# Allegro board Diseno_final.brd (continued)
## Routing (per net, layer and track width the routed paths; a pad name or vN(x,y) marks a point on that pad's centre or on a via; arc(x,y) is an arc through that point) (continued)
N151319: length 8.6
  TOP w0.381: 189.59,27.84 R43.1 ; 189.59,27.84 R42.2 ; 189.59,27.84 190.07,27.36 v1(191.19,27.36)
  BOTTOM w0.381: U164.3 v1(191.19,27.36)
N151343: length 14.8
  TOP w0.381: 264.64,105.77 266.04,104.37 267.11,104.37 269.77,107.04 C134.2 ; 264.64,105.77 264.64,107.48 264.62,107.51 U106.5 ; 264.64,105.77 264.64,103.25
N151347: length 10.8
  TOP w0.381: U36.3 195.25,38.76 189.59,33.1 R43.2
N151351: length 7.3
  TOP w0.381: U36.2 194.59,39.03 194.27,38.71 191.34,38.71 v1(190.8,39.24)
  BOTTOM w0.381: v1(190.8,39.24) R47.2
N151355: length 14.7
  TOP w0.381: 264.62,117.74 264.62,112.9 ; 264.62,117.74 266.09,119.21 266.09,121.77 265.07,122.78 R104.1 ; 264.62,117.74 264.22,118.14 U105.6
N151359: length 13.9
  TOP w0.381: R45.2 195.25,46.25 ; 195.25,46.25 U36.6 ; 195.25,46.25 195.76,45.75 v1(197.33,45.75)
  BOTTOM w0.381: v1(197.33,45.75) 197.33,44.4 196.25,43.32 R47.1
N151379: length 13.2
  TOP w0.381: 195.25,51.64 R45.1 ; 195.25,51.64 195.68,51.21 199.57,51.21 202.34,53.98 C49.1 ; 195.25,51.64 R41.2
N151407: length 35.2
  TOP w0.381: C49.2 202.34,64.69 198.27,68.76 196.01,68.76 195.28,68.02 ; 195.28,69.93 R44.2 ; 195.28,69.93 194.77,70.43 193.27,70.43 v1(190.35,67.51) ; 195.28,69.93 195.28,68.02 ; 195.28,68.02 U35.6
  BOTTOM w0.381: R46.1 v1(190.35,67.51)
N151415: length 12
  TOP w0.381: 257.73,31.22 257.05,31.9 v1(256.41,31.9) ; 257.73,31.22 R106.2 ; 257.73,31.22 R107.1
  BOTTOM w0.381: v1(256.41,31.9) 257.15,31.9 257.68,31.37 ; 257.68,31.37 D27.A ; 257.68,31.37 D28.C
N151419: length 14.2
  TOP w0.381: v1(193.09,59.33) 194.12,59.33 194.61,59.83 U35.2
  BOTTOM w0.381: 190.35,56.59 R46.2 ; 190.35,56.59 R48.1 ; 190.35,56.59 v1(193.09,59.33)
N151447: length 14.6
  TOP w0.381: U35.7 194.61,67.16 194.23,67.54 191.67,67.54 190.58,66.45 C47.2 189.37,65.29 189.36,65.3 v1(187.83,65.3)
  BOTTOM w0.381: v1(187.83,65.3) 187.83,62.8 186.88,61.85 U33.2
N151475: length 15.9
  TOP w0.381: v1(190.86,48.17) C46.2 193.96,46.12 194.59,45.49 U36.7
  BOTTOM w0.381: U32.2 187.34,52.94 188.48,51.8 188.48,48.65 188.96,48.17 v1(190.86,48.17)
N151623: length 32.5
  TOP w0.381: 263.04,108.31 263.04,107.57 262.39,106.92 U104.2 ; 263.04,108.31 263.04,109.58 262.15,110.46 258.08,110.46 256.06,112.48 R108.2 ; 263.04,108.31 262.43,108.92 v1(261.54,108.92)
  BOTTOM w0.381: v1(261.54,108.92) 261.09,108.92 259.46,107.29 259.46,98.65 256.01,95.2 R105.1
N151641: length 8.8
  TOP w0.381: U105.2 257.8,118.8 257.07,119.52 257.07,122.15 257.71,122.78 R104.2
N151661: length 5.1
  TOP w0.381: R108.1 256.06,117.32 256.87,118.14 U105.3
N151733: length 19.9
  TOP w0.381: v1(197.59,39.98) 198.53,39.98 198.54,39.99 C51.2 199.75,38.91 199.11,38.28 196.37,38.28 195.88,38.76 U36.4
  BOTTOM w0.381: U37.4 198.97,49.45 198.48,48.96 198.48,42.19 197.59,41.3 v1(197.59,39.98)
N151737: length 9.2
  TOP w0.381: v1(197.28,57.73) 197.72,58.17 197.72,58.18 198.53,58.99 C54.2 196.68,59.78 195.91,60.54 U35.4
  BOTTOM w0.381: U38.4 198.97,57.76 198.95,57.73 v1(197.28,57.73)
N151741: length 4.2
  TOP w0.381: R44.1 194.21,74.03 194.2,74.02 U34.3
N151759: length 76.9
  TOP w0.381: v1(186.66,73.05) 187.29,73.05 187.31,73.08 U34.5 ; U172.2 124.43,84.45 124.44,84.45 v1(125.07,84.45)
  BOTTOM w0.381: v1(186.66,73.05) 168.43,73.05 164.69,69.32 162.18,69.32 157.12,74.37 145.77,74.37 135.69,84.45 v1(125.07,84.45)
N151833: length 11.6
  TOP w0.381: U107.7 264.64,97.43 265.84,96.24 C133.2 267.6,98.57 267.59,98.58 v1(267.59,99.24)
  BOTTOM w0.381: v1(267.59,99.24) 267.59,100.41 268.55,101.37 U103.2
N152345: length 8.9
  TOP w0.381: R52.2 196.39,27.79 ; 196.39,27.79 R54.1 ; 196.39,27.79 196.8,27.38 v1(197.87,27.38)
  BOTTOM w0.381: U165.3 v1(197.87,27.38)
N152363: length 14.8
  TOP w0.381: 264.64,140.03 U115.2 ; 264.64,140.03 264.64,141.74 264.62,141.77 U114.5 ; 264.64,140.03 266.04,138.63 267.11,138.63 269.77,141.3 C143.2
N152375: length 14.7
  TOP w0.381: 264.62,152.01 266.09,153.48 266.09,156.03 265.07,157.05 R109.1 ; 264.62,152.01 U114.4 ; 264.62,152.01 264.22,152.4 U113.6
N152387: length 59.2
  TOP w0.381: R54.2 196.39,32.87 208.03,44.5 208.03,65.91 195.28,78.66 195.28,79.62 195.25,79.64 U43.3
N152391: length 7.9
  TOP w0.381: U43.2 194.59,79.4 194.26,79.07 191.24,79.07 190.83,79.48 v1(190.83,80.26)
  BOTTOM w0.381: v1(190.83,80.26) 190.83,80.89 190.8,80.91 R56.2
N152399: length 13.9
  TOP w0.381: v1(197.33,86.36) 195.76,86.36 195.25,86.87 ; 195.25,86.87 R50.2 ; 195.25,86.87 U43.6
  BOTTOM w0.381: R56.1 196.25,83.93 197.33,85.01 v1(197.33,86.36)
N152403: length 146.9
  TOP w0.381: 263.98,129.03 263.98,127.61 279.25,112.34 279.25,55.7 262.64,39.09 R111.1 ; 263.98,129.03 264.85,129.9 v1(264.92,129.9) ; 263.98,129.03 U115.6 ; 269.77,149.1 v1(273.63,145.24) ; 269.77,149.1 269.77,149.3 268.38,150.7 266.6,150.7 265.25,149.35 U114.3 ; 269.77,149.1 C143.1
  BOTTOM w0.381: v1(273.63,145.24) 265.91,137.52 265.91,130.89 v1(264.92,129.9)
N152419: length 13.2
  TOP w0.381: 195.25,92.25 195.68,91.82 199.57,91.82 202.34,94.59 C59.1 ; 195.25,92.25 R50.1 ; 195.25,92.25 R51.2
N152423: length 12.8
  TOP w0.381: 195.25,98.5 194.28,97.54 192.25,97.54 191.58,96.86 C60.2 ; 195.25,98.5 R51.1 ; 195.25,98.5 195.28,98.53 U42.3
N152441: length 11.5
  TOP w0.381: R112.1 262.64,31.51 ; 262.64,31.51 262.25,31.89 261.61,31.89 v1(261.57,31.93) ; 262.64,31.51 R111.2
  BOTTOM w0.381: v1(261.57,31.93) 261.61,31.89 262.19,31.89 262.66,31.42 ; 262.66,31.42 D30.C ; 262.66,31.42 D29.A
N152447: length 35.6
  TOP w0.381: 195.28,108.64 195.28,110.54 ; 195.28,108.64 U42.6 ; 195.28,108.64 196.01,109.37 198.27,109.37 202.34,105.31 C59.2 ; 195.28,110.54 194.77,111.05 192.57,111.05 190.35,108.83 v1(190.35,108.2) ; 195.28,110.54 R53.2
  BOTTOM w0.381: R55.1 v1(190.35,108.2)
N152459: length 14.2
  TOP w0.381: U42.2 194.61,100.44 194.12,99.95 v1(193.09,99.95)
  BOTTOM w0.381: 190.35,97.21 R57.1 ; 190.35,97.21 v1(193.09,99.95) ; 190.35,97.21 R55.2
N152487: length 14.4
  TOP w0.381: U42.7 194.61,107.67 194.23,108.05 191.64,108.05 190.58,106.98 C57.2 189.37,105.91 189.36,105.92 v1(187.83,105.92)
  BOTTOM w0.381: v1(187.83,105.92) 187.83,103.42 186.88,102.46 U40.2
N152515: length 15.9
  TOP w0.381: U43.7 194.59,86.11 193.96,86.73 C56.2 v1(190.86,88.79)
  BOTTOM w0.381: v1(190.86,88.79) 188.96,88.79 188.48,89.27 188.48,92.42 187.34,93.56 U39.2
N152649: length 32.5
  TOP w0.381: v1(261.54,143.18) 262.43,143.18 263.04,142.57 ; R113.2 256.06,146.75 258.08,144.73 262.15,144.73 263.04,143.84 263.04,142.57 ; 263.04,142.57 263.04,141.84 262.39,141.19 U112.2
  BOTTOM w0.381: v1(261.54,143.18) 261.09,143.18 259.46,141.55 259.46,132.92 256.01,129.47 R110.1
N152661: length 8.8
  TOP w0.381: U113.2 257.8,153.06 257.07,153.78 257.07,156.41 257.71,157.05 R109.2
N152681: length 5.1
  TOP w0.381: U113.3 256.87,152.4 256.06,151.59 R113.1
N152773: length 19.9
  TOP w0.381: v1(197.59,80.59) 198.53,80.59 198.54,80.6 C61.2 199.75,79.53 199.11,78.89 196.37,78.89 195.88,79.38 U43.4
  BOTTOM w0.381: U44.4 198.97,90.07 198.48,89.57 198.48,82.8 197.59,81.92 v1(197.59,80.59)
N152777: length 9.2
  TOP w0.381: U42.4 195.91,101.16 196.68,100.38 197.31,100.38 197.32,100.39 C64.2 198.53,99.6 197.72,98.8 197.72,98.79 v1(197.28,98.35)
  BOTTOM w0.381: U45.4 198.97,98.37 198.95,98.35 v1(197.28,98.35)
N152781: length 4.2
  TOP w0.381: U41.3 194.2,114.63 194.21,114.64 R53.1
N152799: length 81.5
  TOP w0.381: U173.2 112.9,110.54 115.27,108.18 130.28,108.18 v1(131.32,109.22) ; U41.5 v1(186.87,113.69)
  BOTTOM w0.381: v1(186.87,113.69) 170.08,113.69 165.61,109.22 v1(131.32,109.22)
N152853: length 11.6
  TOP w0.381: v1(267.59,133.5) 267.59,132.85 267.6,132.84 C142.2 265.84,130.51 264.64,131.7 U115.7
  BOTTOM w0.381: U111.2 268.55,135.64 267.59,134.67 v1(267.59,133.5)
N153383: length 14.8
  TOP w0.381: C152.2 269.77,175.34 267.11,172.67 266.04,172.67 264.64,174.07 ; U122.5 264.62,175.81 264.64,175.78 264.64,174.07 ; 264.64,174.07 U123.2
N153389: length 9
  TOP w0.381: 203,27.76 R63.1 ; 203,27.76 R59.2 ; 203,27.76 203.38,27.38 v1(204.47,27.38)
  BOTTOM w0.381: U166.3 v1(204.47,27.38)
N153395: length 14.7
  TOP w0.381: R114.1 265.07,191.08 266.09,190.07 266.09,187.52 264.62,186.04 ; 264.62,186.04 264.22,186.44 U121.6 ; 264.62,186.04 U122.4
N153423: length 182.6
  TOP w0.381: v1(273.93,179.29) 273.49,179.73 273.44,179.73 269.82,183.34 269.77,183.34 ; U122.3 265.25,183.39 266.6,184.73 268.38,184.73 269.77,183.34 ; 269.77,183.34 C152.1 ; 263.98,163.07 263.98,161.29 283.44,141.83 283.44,56.21 268.17,40.94 R116.1 ; 263.98,163.07 264.85,163.93 v1(264.92,163.93) ; 263.98,163.07 U123.6
  BOTTOM w0.381: v1(273.93,179.29) 273.49,178.85 273.49,178.85 265.91,171.27 265.91,164.92 v1(264.92,163.93)
N153431: length 99.9
  TOP w0.381: U50.3 195.25,119.56 211.58,103.23 211.58,41.91 203,33.32 R63.2
N153435: length 7.6
  TOP w0.381: v1(190.8,120.95) 190.8,120.14 191.19,119.76 194.21,119.76 194.59,120.14 U50.2
  BOTTOM w0.381: v1(190.8,120.95) R65.2
N153443: length 13.9
  TOP w0.381: 195.25,127.41 R61.2 ; 195.25,127.41 195.76,126.9 v1(197.33,126.9) ; 195.25,127.41 U50.6
  BOTTOM w0.381: R65.1 196.25,124.47 197.33,125.55 v1(197.33,126.9)
N153455: length 12.9
  TOP w0.381: 268.17,31.29 R116.2 ; 268.17,31.29 267.54,31.93 v1(266.67,31.93) ; 268.17,31.29 R117.1
  BOTTOM w0.381: 268.17,31.32 D31.A ; 268.17,31.32 D32.C ; 268.17,31.32 267.56,31.93 v1(266.67,31.93)
N153463: length 13.2
  TOP w0.381: 195.25,132.79 R61.1 ; 195.25,132.79 R62.2 ; 195.25,132.79 195.68,132.36 199.57,132.36 202.34,135.13 C69.1
N153467: length 12.8
  TOP w0.381: R62.1 195.25,139.04 ; 195.25,139.04 194.28,138.07 192.25,138.07 191.58,137.4 C70.2 ; 195.25,139.04 195.28,139.06 U49.3
N153491: length 34.9
  TOP w0.381: 195.28,149.17 196.01,149.91 198.27,149.91 202.34,145.85 C69.2 ; 195.28,149.17 U49.6 ; 195.28,149.17 195.28,151.08 ; v1(190.35,148.41) 193.34,151.41 194.94,151.41 195.28,151.08 ; 195.28,151.08 R60.2
  BOTTOM w0.381: R64.1 v1(190.35,148.41)
N153503: length 14.2
  TOP w0.381: v1(193.09,140.49) 194.12,140.49 194.61,140.98 U49.2
  BOTTOM w0.381: v1(193.09,140.49) 190.35,137.74 ; 190.35,137.74 R64.2 ; 190.35,137.74 R66.1
N153531: length 14.7
  TOP w0.381: v1(187.83,146.46) 189.36,146.46 189.37,146.45 C67.2 190.58,147.47 191.92,148.82 194.23,148.82 194.61,148.44 U49.7
  BOTTOM w0.381: v1(187.83,146.46) 187.83,143.95 186.88,143 U47.2
N153559: length 15.9
  TOP w0.381: v1(190.86,129.32) C66.2 193.96,127.27 194.59,126.64 U50.7
  BOTTOM w0.381: v1(190.86,129.32) 188.96,129.32 188.48,129.81 188.48,132.96 187.34,134.09 U46.2
N153663: length 32.5
  TOP w0.381: 263.04,176.61 262.43,177.22 v1(261.54,177.22) ; 263.04,176.61 263.04,177.88 262.15,178.77 258.08,178.77 256.06,180.78 R118.2 ; 263.04,176.61 263.04,175.87 262.39,175.22 U120.2
  BOTTOM w0.381: v1(261.54,177.22) 261.09,177.22 259.46,175.59 259.46,166.95 256.01,163.5 R115.1
N153681: length 8.8
  TOP w0.381: R114.2 257.71,191.08 257.07,190.45 257.07,187.82 257.8,187.1 U121.2
N153701: length 5.1
  TOP w0.381: U121.3 256.87,186.44 256.06,185.62 R118.1
N153817: length 19.9
  TOP w0.381: U50.4 195.88,119.91 196.37,119.43 199.11,119.43 199.75,120.07 C71.2 198.54,121.14 198.53,121.13 v1(197.59,121.13)
  BOTTOM w0.381: v1(197.59,121.13) 197.59,122.45 198.48,123.34 198.48,130.11 198.97,130.61 U51.4
N153821: length 9.2
  TOP w0.381: U49.4 195.91,141.69 196.68,140.93 C74.2 198.53,140.14 197.72,139.34 197.72,139.33 v1(197.28,138.89)
  BOTTOM w0.381: U52.4 198.97,138.91 198.95,138.89 v1(197.28,138.89)
N153825: length 4.2
  TOP w0.381: U48.3 194.2,155.17 194.21,155.18 R60.1
N153843: length 78.8
  TOP w0.381: U174.2 122.65,140.77 122.66,140.77 v1(123.34,140.77) ; U48.5 v1(186.08,154.23)
  BOTTOM w0.381: v1(186.08,154.23) 170.05,154.23 165.91,150.09 162.59,150.09 157.56,155.12 156.54,155.12 155.7,154.28 145.92,154.28 132.41,140.77 v1(123.34,140.77)
N153873: length 11.6
  TOP w0.381: U123.7 264.64,165.74 265.84,164.54 C151.2 267.6,166.87 267.59,166.88 v1(267.59,167.54)
  BOTTOM w0.381: v1(267.59,167.54) 267.59,168.71 268.55,169.67 U119.2
N154443: length 8.3
  TOP w0.381: R72.1 209.22,27.74 ; 209.22,27.74 209.58,27.38 v1(210.44,27.38) ; 209.22,27.74 R71.2
  BOTTOM w0.381: v1(210.44,27.38) 209.64,27.38 209.61,27.41 U167.3
N154471: length 142.2
  TOP w0.381: U56.3 195.25,161.06 215.65,140.67 215.65,40.26 209.22,33.83 R72.2
N154475: length 8
  TOP w0.381: U56.2 194.59,161.61 193.81,160.83 191.34,160.83 v1(190.8,161.37)
  BOTTOM w0.381: v1(190.8,161.37) R74.2
N154483: length 13.9
  TOP w0.381: R69.2 195.25,168.83 ; 195.25,168.83 195.76,168.33 v1(197.33,168.33) ; 195.25,168.83 195.25,167
  BOTTOM w0.381: v1(197.33,168.33) 197.33,166.98 196.25,165.9 R74.1
N154503: length 13.2
  TOP w0.381: 195.25,174.22 R69.1 ; 195.25,174.22 195.68,173.79 199.57,173.79 202.34,176.56 C79.1 ; 195.25,174.22 R70.2
N154507: length 12.8
  TOP w0.381: R70.1 195.25,180.47 ; 195.25,180.47 195.28,180.49 U57.3 ; 195.25,180.47 194.28,179.5 192.25,179.5 191.58,178.83 C80.2
N154531: length 35.1
  TOP w0.381: C79.2 202.34,187.27 198.27,191.34 196.01,191.34 195.28,190.6 ; 195.28,190.6 U57.6 ; 195.28,190.6 195.28,192.51 ; 195.28,192.51 R68.2 ; 195.28,192.51 194.77,193.01 v1(193.4,193.01)
  BOTTOM w0.381: R73.1 190.35,189.97 v1(193.4,193.01)
N154543: length 14.2
  TOP w0.381: U57.2 194.61,182.41 194.12,181.91 v1(193.09,181.91)
  BOTTOM w0.381: v1(193.09,181.91) 190.35,179.17 ; 190.35,179.17 R75.1 ; 190.35,179.17 R73.2
N154571: length 15.7
  TOP w0.381: v1(187.83,187.88) 189.36,187.88 189.37,187.87 C77.2 190.58,189.87 191.34,190.63 194.01,190.63 194.61,190.02 U57.7
  BOTTOM w0.381: U54.2 186.88,184.43 187.83,185.38 v1(187.83,187.88)
N154599: length 15.9
  TOP w0.381: 194.59,167 194.59,168.07 193.96,168.7 C76.2 v1(190.86,170.75)
  BOTTOM w0.381: U53.2 187.34,175.52 188.48,174.38 188.48,171.23 188.96,170.75 v1(190.86,170.75)
N154857: length 19.9
  TOP w0.381: v1(197.59,162.56) 198.53,162.56 198.54,162.57 C81.2 199.75,161.49 199.11,160.86 196.37,160.86 195.88,161.34 U56.4
  BOTTOM w0.381: v1(197.59,162.56) 197.59,163.88 198.48,164.77 198.48,171.54 198.97,172.03 U58.4
N154861: length 9.2
  TOP w0.381: v1(197.28,180.31) 197.72,180.75 197.72,180.76 198.53,181.57 C84.2 196.56,182.36 195.91,183.01 U57.4
  BOTTOM w0.381: v1(197.28,180.31) 198.95,180.31 198.97,180.34 U59.4
N154865: length 4.2
  TOP w0.381: R68.1 194.21,196.61 194.2,196.6 U55.3
N154883: length 80.2
  TOP w0.381: v1(183.74,194.84) 184.56,195.66 U55.5 ; U175.2 123.18,168.94 123.18,168.93 v1(123.87,168.93)
  BOTTOM w0.381: v1(123.87,168.93) 125.07,168.93 147.04,190.91 159.89,190.91 163.83,194.84 v1(183.74,194.84)
N183704: length 133.9
  TOP w0.381: v1(234.95,83.74) 234.31,83.74 233.38,82.8 U65.2 ; v1(121.67,96.8) U176.4
  BOTTOM w0.381: v1(121.67,96.8) 128.85,96.8 147.08,78.57 165.7,78.57 167.84,76.43 193.45,76.43 197.08,72.8 198.25,72.8 209.19,83.74 230.89,83.74 230.91,83.76 231.42,83.76 231.44,83.74 v1(234.95,83.74)
N189418: length 4.1
  TOP w0.381: U168.4 106.62,84.04 105.23,82.65 R4.1
N189529: length 12.8
  TOP w0.381: R40.1 105.04,85.14 105.29,85.39 U172.4
N189636: length 13.4
  TOP w0.381: U169.4 113.82,114.12 112.14,112.45 R13.1
N189665: length 4.1
  TOP w0.381: U173.4 106.35,111.48 105.05,110.19 R49.1
N189787: length 4
  TOP w0.381: R22.1 105.67,137.97 106.69,138.99 U170.4
N189811: length 13.4
  TOP w0.381: U174.4 115.4,141.71 113.72,140.03 R58.1
N189953: length 3.7
  TOP w0.381: R31.1 105.04,173.08 105.3,173.34 U171.4
N189979: length 13.8
  TOP w0.381: R67.1 104.97,168.33 105.35,167.94 113,167.94 114.94,169.88 U175.4
N190257: length 129.3
  TOP w0.381: v1(122.63,125.19) 121.98,125.19 121.97,125.18 U177.4 ; v1(234.95,115.42) 234.31,115.42 233.38,114.48 233.38,112.9
  BOTTOM w0.381: v1(122.63,125.19) 130.81,125.19 136.91,119.1 190.7,119.1 201.51,108.3 202.35,108.3 209.83,115.77 233.97,115.77 234.33,115.42 v1(234.95,115.42)
N190390: length 177.4
  TOP w0.381: U180.4 111.19,102.2 111.2,102.18 v1(113.44,102.18) ; v1(267.49,83.74) 266.85,83.74 265.91,82.8 U98.2
  BOTTOM w0.381: v1(267.49,83.74) 265.73,83.74 259.38,90.09 214.45,90.09 203.68,79.32 147.6,79.32 124.74,102.18 v1(113.44,102.18)
N190419: length 131.7
  TOP w0.381: v1(234.95,149.68) 234.31,149.68 233.38,148.74 U81.2 ; U178.4 123.15,153.34 123.15,153.34 v1(123.77,153.34)
  BOTTOM w0.381: v1(123.77,153.34) 139.5,153.34 146.53,160.38 164.11,160.38 167.08,157.4 193.27,157.4 199.8,150.88 201.83,150.88 208.23,157.28 227.36,157.28 v1(234.95,149.68)
N190547: length 170.2
  TOP w0.381: v1(267.49,115.42) 266.85,115.42 265.91,114.48 265.91,112.9 ; v1(112.88,129.67) 111.2,129.67 111.19,129.67 U181.4
  BOTTOM w0.381: v1(112.88,129.67) 127.41,129.67 137.34,119.74 206.71,119.74 209.93,116.51 237.19,116.51 241.45,120.78 259.92,120.78 265.28,115.42 v1(267.49,115.42)
N190594: length 131.9
  TOP w0.381: U90.2 233.38,182.78 234.31,183.72 v1(234.95,183.72) ; v1(124.59,181.52) 123.97,181.52 123.95,181.51 U179.4
  BOTTOM w0.381: v1(234.95,183.72) 231.93,183.72 217.55,198.09 149.81,198.09 133.24,181.52 v1(124.59,181.52)
N190692: length 172.3
  TOP w0.381: v1(113.44,157.18) 111.21,157.18 111.19,157.15 U182.4 ; v1(267.49,149.68) 266.85,149.68 265.91,148.74 U114.2
  BOTTOM w0.381: v1(267.49,149.68) 264.39,149.68 256.08,157.99 207.87,157.99 201.6,151.71 199.95,151.71 193.55,158.12 167.46,158.12 164.49,161.09 146.23,161.09 142.32,157.18 v1(113.44,157.18)
N190839: length 172.9
  TOP w0.381: U183.4 113.89,184.63 113.89,184.62 v1(114.66,184.62) ; v1(267.49,183.72) 266.85,183.72 265.91,182.78 U122.2
  BOTTOM w0.381: v1(267.49,183.72) 252.37,198.83 149.58,198.83 135.37,184.62 v1(114.66,184.62)
N222678: length 13.8
  TOP w0.381: v1(226.31,79.81) 226.31,80.87 226.3,80.89 C91.2 226.3,83.3 224.74,84.85 224.74,85.47 225.09,85.83 U66.4
  BOTTOM w0.381: v1(226.31,79.81) 226.31,78.97 224.99,77.65 U68.4
N222700: length 13.8
  TOP w0.381: U97.4 257.63,85.83 257.28,85.47 257.28,84.85 258.84,83.3 C127.2 258.84,80.89 258.85,80.87 v1(258.85,79.81)
  BOTTOM w0.381: v1(258.85,79.81) 258.85,78.97 257.53,77.65 U100.4
N224115: length 12.2
  TOP w0.381: v1(257.23,70.26) 258.11,70.26 258.12,70.25 C129.2 259.64,71.32 261.52,73.2 262.97,73.2 263.35,72.82 U99.4
  BOTTOM w0.381: U101.4 v1(257.23,70.26)
N224126: length 12.2
  TOP w0.381: U67.4 230.81,72.82 230.43,73.2 228.98,73.2 227.1,71.32 C93.2 225.59,70.25 225.58,70.26 v1(224.69,70.26)
  BOTTOM w0.381: U69.4 v1(224.69,70.26)
N225476: length 13.9
  TOP w0.381: U73.4 225.09,117.5 224.74,117.15 224.74,116.53 226.3,114.97 C100.2 226.3,112.56 226.31,112.55 v1(226.31,111.15)
  BOTTOM w0.381: U76.4 225.11,109.32 226.31,110.53 v1(226.31,111.15)
N225794: length 13.8
  TOP w0.381: U105.4 257.63,117.5 257.28,117.15 257.28,116.53 258.84,114.97 C136.2 258.84,112.56 258.85,112.55 v1(258.85,111.48)
  BOTTOM w0.381: U108.4 257.53,109.32 258.85,110.64 v1(258.85,111.48)
N226643: length 12.2
  TOP w0.381: v1(224.69,101.93) 225.58,101.93 225.59,101.92 C102.2 227.1,103 228.98,104.88 230.43,104.88 230.81,104.5 230.81,103.25
  BOTTOM w0.381: U77.4 v1(224.69,101.93)
N226662: length 12.2
  TOP w0.381: v1(257.23,101.93) 258.11,101.93 258.12,101.92 C138.2 259.64,103 261.52,104.88 262.97,104.88 263.35,104.5 263.35,103.25
  BOTTOM w0.381: U109.4 v1(257.23,101.93)
N227931: length 13.8
  TOP w0.381: v1(226.31,145.75) 226.31,146.81 226.3,146.83 C109.2 226.3,149.23 224.74,150.79 224.74,151.41 225.09,151.76 U83.4
  BOTTOM w0.381: v1(226.31,145.75) 226.31,144.91 224.99,143.59 U84.4
N229062: length 12.2
  TOP w0.381: U82.4 230.81,138.76 230.43,139.14 228.98,139.14 227.1,137.26 C111.2 225.59,136.19 225.58,136.19 v1(224.69,136.19)
  BOTTOM w0.381: U85.4 v1(224.69,136.19)
N230061: length 13.8
  TOP w0.381: v1(226.31,179.78) 226.31,180.85 226.3,180.86 C118.2 226.3,183.27 224.74,184.83 224.74,185.45 225.09,185.8 U89.4
  BOTTOM w0.381: v1(226.31,179.78) 226.31,178.94 224.99,177.62 U92.4
N231120: length 12.2
  TOP w0.381: v1(224.69,170.23) 225.58,170.23 225.59,170.22 C120.2 227.1,171.3 228.98,173.18 230.43,173.18 230.81,172.8 U91.4
  BOTTOM w0.381: U93.4 v1(224.69,170.23)
N231215: length 13.8
  TOP w0.381: U121.4 257.63,185.8 257.28,185.45 257.28,184.83 258.84,183.27 C154.2 258.84,180.86 258.85,180.85 v1(258.85,179.78)
  BOTTOM w0.381: U124.4 257.53,177.62 258.85,178.94 v1(258.85,179.78)
N232018: length 12.2
  TOP w0.381: v1(257.23,170.23) 258.11,170.23 258.12,170.22 C156.2 259.64,171.3 261.52,173.18 262.97,173.18 263.35,172.8 U123.4
  BOTTOM w0.381: 254.43,170.23 v1(257.23,170.23)
N233016: length 13.8
  TOP w0.381: U113.4 257.63,151.76 257.28,151.41 257.28,150.79 258.84,149.23 C145.2 258.84,146.83 258.85,146.81 v1(258.85,145.75)
  BOTTOM w0.381: v1(258.85,145.75) 258.85,144.91 257.53,143.59 U116.4
N233815: length 12.2
  TOP w0.381: U115.4 263.35,138.76 262.97,139.14 261.52,139.14 259.64,137.26 C147.2 258.12,136.19 258.11,136.19 v1(257.23,136.19)
  BOTTOM w0.381: U117.4 v1(257.23,136.19)

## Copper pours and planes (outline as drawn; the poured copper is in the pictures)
3V3 on VCC: 137.31,63.07 123.9,63.07 124.1,63.27 124.1,188.72 104.5,188.72 104.47,188.7 104.47,164.16 52.98,164.16 52.27,163.45 52.27,144.27 53.59,142.95 104.37,142.95 104.47,143.05 104.47,63.09 19.53,63.09 19.51,63.12 19.51,12.98 19.89,12.6 135.81,12.6 137.72,14.5 137.72,62.66
3V3ADC on VCC: 156.16,197.84 156.11,197.89 155.91,197.69 155.91,68.3 161.85,68.3 161.98,68.43 161.98,195.07 161.9,195.15 191.19,195.15 191.26,195.07 191.26,68.5 191.47,68.3 196.27,68.3 196.47,68.5 196.47,197.54 196.16,197.84
3V3DAC on VCC: 266.78,174.24 266.78,57.15 266.8,57.12 275.31,57.12 275.31,177.67 234.26,177.67 234.19,177.6 234.19,175.41 234.15,175.37 234.15,57.62 234.49,57.28 240.44,57.28 240.44,174.24
5VU on VCC: 40.51,192.53 41.81,191.24 41.81,121.74 41.4,121.34 13.44,121.34 12.37,122.4 12.37,144.86 12.45,144.93 12.45,191.69 13.3,192.54 13.31,192.53
5VU on VCC: 272.8,12.73 272.8,22.25 272.67,22.38 180.59,22.38 180.59,22.33 180.64,22.28 179.91,21.54 142.32,21.54 141.76,22.1 141.76,189.79 141.35,190.2 141.35,190.22 125.63,190.22 124.87,189.46 124.87,64.59 125.43,64.03 137.69,64.03 138.4,63.32 138.4,13.34 139.01,12.73 272.36,12.73 272.77,13.13 272.77,12.7
+5V on VCC: 277.29,177.62 285.57,177.62 285.57,177.57 286.13,177.01 286.13,42.72 284.96,41.55 180.26,41.55 180.14,41.68 179.63,41.17 179.63,22.86 178.74,21.97 142.54,21.97 142.06,22.45 142.06,189.79 142.1,189.83 142.1,190.28 141.87,190.51 104.15,190.51 102.34,188.7 102.34,182.5 101.57,181.74 54.74,181.74 53.31,183.16 53.31,192.91 54.86,194.46 145.52,194.46 150.37,189.61 150.37,32.16 150.44,32.08 154,32.08 154.23,31.85 154.23,27.66 154.38,27.51 154.38,27.48 170.64,27.48 171.2,28.04 171.2,186.92 171.53,187.25 178.79,187.25 179.07,186.97 179.07,48.97 180.19,47.85 243.48,47.85 244.2,48.56 244.2,169.75 244.17,169.77 244.4,170 249.45,170 249.73,169.72 249.73,54.76 250.09,54.41 275.21,54.41 276.58,55.78 276.58,176.99 276.66,176.99
-5V on VCC: 241.22,173.84 257.91,173.84 257.94,173.86 257.94,55.75 257.76,55.58 252.78,55.58 252.55,55.8 252.55,170.31 244.12,170.31 243.84,170.03 243.84,54.03 243.61,53.8 218.41,53.8 218.41,176.28 218.44,176.3 225.48,176.3 225.48,175.95 225.46,175.96 225.46,173.06 225.5,173.02 225.5,56.41 240.84,56.41 241.2,56.06 241.2,173.86
-5V on VCC: 196.82,188.9 225.27,188.9 225.48,189.1 225.48,176.3 225.43,176.25 204.32,176.25 204.24,176.33 204.24,51.33 204.06,51.16 181.74,51.16 181.71,51.18 181.76,51.23 181.76,188.87 181.64,189 169.75,189 169.77,188.98 169.77,51.41 169.85,51.33 169.85,28.68 155.32,28.68 155.32,32.54 155.27,32.59 150.77,32.59 150.67,32.69 150.67,35.59 151.13,35.59 151.13,189.76 151.03,189.76 145.77,195.02 53.67,195.02 51.36,192.71 51.36,183.03 54.89,179.5 64.64,179.5 65.41,178.74 65.41,170.59 64.39,169.57 43.36,169.57 42.44,170.48 42.44,199.39 155.37,199.39 155.65,199.11 155.65,67.84 155.96,67.54 161.34,67.54 161.35,67.53 162.37,67.53 162.38,67.51 162.41,67.51 162.86,67.97 162.86,194.41 189.13,194.41 189.2,194.34 189.2,60.5 189.43,60.27 196.8,60.27 196.8,188.93
A_GND on GND: 286.59,199.39 286.59,12.29 286.41,12.12 261.92,12.12 261.9,12.14 261.9,18.72 251.21,18.72 251.21,12.14 239.06,12.14 239.06,18.8 228.35,18.8 228.35,12.17 202.51,12.17 202.49,12.19 202.49,18.85 191.72,18.85 191.72,12.19 179.6,12.19 179.6,18.85 168.91,18.85 168.91,12.24 141.63,12.24 141.47,12.41 141.47,191.39 82.27,191.39 82.25,191.41 82.25,169.16 80.87,167.79 49.38,167.79 48.39,168.78 48.39,182.52 47.65,183.26 13.36,183.26 12.65,183.97 12.65,198.81 13.49,199.64 141.43,199.64 141.47,199.61 141.47,199.38 141.48,199.39
A_GND on GND: 139.75,12.55 13.03,12.55 12.32,13.26 12.32,143.26 12.57,143.51 46.48,143.51 46.79,143.81 46.79,166.04 47.02,166.27 85.22,166.27 86.11,167.16 86.11,189.38 86.49,189.76 139.75,189.76 140.03,189.48 140.03,12.83
A_GND on GND: 12.52,182.96 41.55,182.96 42.6,181.91 42.6,144.42 41.88,143.71 13.31,143.71 12.32,144.7 12.32,182.75
